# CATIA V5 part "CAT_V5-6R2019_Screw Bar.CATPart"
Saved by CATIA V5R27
Part number: Screw Bar
Bounding box of the stored display mesh (mm): x -3 to 3, y -52 to 52, z -3 to 3
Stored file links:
  E:\_Deepak\2017_Deepak\CATIA\Resources\Tutorial Files\Tutorials\c16_catia_v5_6r2016_tut\Bench vice\CAT_V5-6R2016_Screw Bar.CATPart
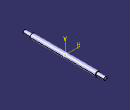
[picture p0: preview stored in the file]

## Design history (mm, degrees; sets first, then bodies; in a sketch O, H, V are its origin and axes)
Body1 (main body)
  Sketch1 on zx-plane, origin (0, 0, 0), H (-1, 0, 0), V (0, 0, 1)
    circle A1 centre (0, 0) radius 2
    radius A1 = 2
  Sketch2 on zx-plane, origin (0, 0, 0), H (-1, 0, 0), V (0, 0, 1)
    circle A1 centre (0, 0) radius 3
    radius A1 = 3
  Pad1: profile Sketch1, direction (0, 1, 0), length 52, mirrored extent
  Pad2: profile Sketch2, direction (0, 1, 0), length 42, mirrored extent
